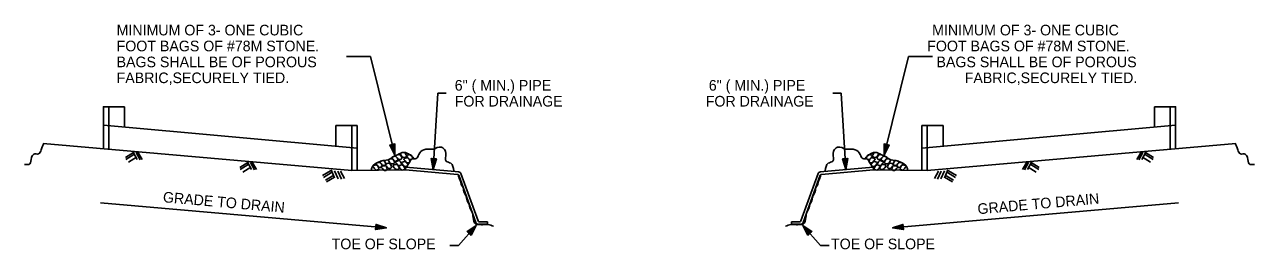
# Model space of a CAD drawing. Extents: x -41 to 191, y -168 to 6.
# Drawn here: x -40.56 to -7.34, y -129.27 to -123.2 of the extents above; entities that cross this region are included whole.
import ezdxf

# ---------------------------------------------------------------- set-up
doc = ezdxf.new("R2010")
doc.units = 0
for name, color, linetype in [('Arrowhead Terminators CELL', 7, 'Continuous'), ('Default', 7, 'Continuous'), ('Dimension Lines CELL', 7, 'Continuous'), ('Mis Object Lines', 7, 'Continuous'), ('Text CELL', 7, 'Continuous')]:
    doc.layers.add(name, color=color, linetype=linetype)

msp = doc.modelspace()

# ---------------------------------------------------------------- linework, layer by layer
at = {"layer": 'Arrowhead Terminators CELL'}
for points in [[(-30.624, -126.441), (-30.638, -126.445), (-30.554, -126.719), (-30.651, -126.448), (-30.665, -126.451), (-30.554, -126.719), (-30.679, -126.455), (-30.693, -126.458), (-30.554, -126.719), (-30.554, -126.424), (-30.568, -126.427), (-30.554, -126.719), (-30.582, -126.431), (-30.596, -126.434), (-30.554, -126.719), (-30.61, -126.438), (-30.693, -126.458), (-30.554, -126.424), (-30.554, -126.719), (-30.693, -126.458)], [(-17.277, -126.441), (-17.263, -126.445), (-17.347, -126.719), (-17.249, -126.448), (-17.236, -126.451), (-17.347, -126.719), (-17.222, -126.455), (-17.208, -126.458), (-17.347, -126.719), (-17.347, -126.424), (-17.333, -126.427), (-17.347, -126.719), (-17.319, -126.431), (-17.305, -126.434), (-17.347, -126.719), (-17.291, -126.438), (-17.208, -126.458), (-17.347, -126.424), (-17.347, -126.719), (-17.208, -126.458)], [(-29.507, -126.822), (-29.521, -126.821), (-29.524, -127.108), (-29.535, -126.82), (-29.549, -126.819), (-29.524, -127.108), (-29.564, -126.819), (-29.578, -126.818), (-29.524, -127.108), (-29.435, -126.826), (-29.449, -126.825), (-29.524, -127.108), (-29.464, -126.825), (-29.478, -126.824), (-29.524, -127.108), (-29.492, -126.823), (-29.578, -126.818), (-29.435, -126.826), (-29.524, -127.108), (-29.578, -126.818)], [(-18.394, -126.822), (-18.38, -126.821), (-18.377, -127.108), (-18.366, -126.82), (-18.352, -126.819), (-18.377, -127.108), (-18.337, -126.819), (-18.323, -126.818), (-18.377, -127.108), (-18.466, -126.826), (-18.452, -126.825), (-18.377, -127.108), (-18.437, -126.825), (-18.423, -126.824), (-18.377, -127.108), (-18.409, -126.823), (-18.323, -126.818), (-18.466, -126.826), (-18.377, -127.108), (-18.323, -126.818)], [(-31.073, -128.664), (-31.074, -128.679), (-30.787, -128.689), (-31.075, -128.693), (-31.076, -128.707), (-30.787, -128.689), (-31.077, -128.721), (-31.079, -128.736), (-30.787, -128.689), (-31.066, -128.593), (-31.068, -128.607), (-30.787, -128.689), (-31.069, -128.622), (-31.07, -128.636), (-30.787, -128.689), (-31.071, -128.65), (-31.079, -128.736), (-31.066, -128.593), (-30.787, -128.689), (-31.079, -128.736)], [(-28.553, -128.836), (-28.543, -128.845), (-28.364, -128.621), (-28.532, -128.855), (-28.521, -128.864), (-28.364, -128.621), (-28.511, -128.874), (-28.5, -128.883), (-28.364, -128.621), (-28.607, -128.788), (-28.596, -128.798), (-28.364, -128.621), (-28.586, -128.807), (-28.575, -128.817), (-28.364, -128.621), (-28.564, -128.826), (-28.5, -128.883), (-28.607, -128.788), (-28.364, -128.621), (-28.5, -128.883)], [(-19.348, -128.836), (-19.358, -128.845), (-19.537, -128.621), (-19.369, -128.855), (-19.38, -128.864), (-19.537, -128.621), (-19.39, -128.874), (-19.401, -128.883), (-19.537, -128.621), (-19.294, -128.788), (-19.305, -128.798), (-19.537, -128.621), (-19.315, -128.807), (-19.326, -128.817), (-19.537, -128.621), (-19.337, -128.826), (-19.401, -128.883), (-19.294, -128.788), (-19.537, -128.621), (-19.401, -128.883)], [(-16.828, -128.664), (-16.827, -128.679), (-17.114, -128.689), (-16.826, -128.693), (-16.825, -128.707), (-17.114, -128.689), (-16.824, -128.721), (-16.822, -128.736), (-17.114, -128.689), (-16.835, -128.593), (-16.833, -128.607), (-17.114, -128.689), (-16.832, -128.622), (-16.831, -128.636), (-17.114, -128.689), (-16.83, -128.65), (-16.822, -128.736), (-16.835, -128.593), (-17.114, -128.689), (-16.822, -128.736)]]:
    msp.add_lwpolyline(points, dxfattribs=at)
at = {"layer": 'Default'}
for p, q in [((-38.286, -126.575), (-38.286, -125.421)), ((-38.286, -125.421), (-37.857, -125.421)), ((-9.615, -125.421), (-10.044, -125.421)), ((-9.615, -126.575), (-9.615, -125.421)), ((-32.147, -125.927), (-31.717, -125.927)), ((-31.717, -125.927), (-31.717, -127.14)), ((-31.717, -125.927), (-31.574, -125.927)), ((-31.574, -125.927), (-31.574, -127.14)), ((-16.184, -125.927), (-16.327, -125.927)), ((-16.327, -125.927), (-16.327, -127.14)), ((-15.754, -125.927), (-16.184, -125.927)), ((-16.184, -125.927), (-16.184, -127.14)), ((-30.267, -127.122), (-31.723, -127.136)), ((-30.261, -127.051), (-30.267, -127.122)), ((-28.863, -127.245), (-30.267, -127.122)), ((-30.261, -127.051), (-28.834, -127.175)), ((-17.64, -127.051), (-19.067, -127.175)), ((-19.038, -127.245), (-17.634, -127.122)), ((-17.64, -127.051), (-17.634, -127.122)), ((-17.634, -127.122), (-16.178, -127.136)), ((-28.833, -127.268), (-28.368, -128.545)), ((-28.773, -127.222), (-28.309, -128.497)), ((-19.128, -127.222), (-19.592, -128.497)), ((-19.068, -127.268), (-19.533, -128.545)), ((-28.276, -128.521), (-28.055, -128.521)), ((-28.055, -128.521), (-28.055, -128.592)), ((-19.625, -128.521), (-19.846, -128.521)), ((-19.846, -128.521), (-19.846, -128.592)), ((-28.301, -128.592), (-28.055, -128.592)), ((-19.6, -128.592), (-19.846, -128.592))]:
    msp.add_line(p, q, dxfattribs=at)
for points in [[(-38.429, -126.558), (-38.429, -125.421), (-38.286, -125.421), (-38.286, -125.425)], [(-9.472, -126.558), (-9.472, -125.421), (-9.615, -125.421), (-9.615, -125.425)], [(-40.051, -126.408), (-31.723, -127.136)], [(-7.85, -126.408), (-16.178, -127.136)]]:
    msp.add_lwpolyline(points, dxfattribs=at)
for centre, radius, start, end in [((-28.841, -127.247), 0.0716, 20.0004, 85.0001), ((-19.06, -127.247), 0.0716, 94.9999, 159.9996), ((-28.866, -127.28), 0.0358, 20, 85), ((-19.035, -127.28), 0.0358, 95, 160), ((-28.276, -128.485), 0.0358, 200.0006, 270), ((-19.625, -128.485), 0.0358, 270, 339.9994), ((-28.301, -128.521), 0.0716, 200.0001, 270), ((-19.6, -128.521), 0.0716, 270, 339.9999)]:
    msp.add_arc(centre, radius, start, end, dxfattribs=at)
for points in [[(-40.037, -126.4), (-40.107, -126.58), (-40.177, -126.689), (-40.307, -126.699), (-40.367, -126.789), (-40.417, -126.959), (-40.557, -126.979)], [(-28.968, -127.144), (-29.047, -126.944), (-29.169, -126.889), (-29.181, -126.682), (-29.302, -126.506), (-29.527, -126.561), (-29.655, -126.561), (-29.776, -126.579), (-29.91, -126.707), (-29.983, -126.816), (-30.086, -126.828), (-30.165, -126.925), (-30.25, -127.047)], [(-18.933, -127.144), (-18.854, -126.944), (-18.732, -126.889), (-18.72, -126.682), (-18.599, -126.506), (-18.374, -126.561), (-18.246, -126.561), (-18.125, -126.579), (-17.991, -126.707), (-17.918, -126.816), (-17.815, -126.828), (-17.736, -126.925), (-17.651, -127.047)], [(-7.864, -126.4), (-7.794, -126.58), (-7.724, -126.689), (-7.594, -126.699), (-7.534, -126.789), (-7.484, -126.959), (-7.344, -126.979)], [(-30.05, -126.81), (-30.159, -126.707), (-30.305, -126.652), (-30.487, -126.713), (-30.597, -126.761), (-30.712, -126.84), (-30.87, -126.871), (-31.022, -126.925), (-31.156, -127.023), (-31.192, -127.12)], [(-30.566, -126.919), (-30.627, -126.828), (-30.682, -126.828), (-30.737, -126.865), (-30.718, -126.889), (-30.682, -126.932), (-30.639, -126.962), (-30.579, -126.944), (-30.566, -126.925)], [(-30.469, -126.853), (-30.53, -126.761), (-30.585, -126.761), (-30.639, -126.798), (-30.621, -126.822), (-30.585, -126.865), (-30.542, -126.895), (-30.481, -126.877), (-30.469, -126.859)], [(-30.378, -126.962), (-30.439, -126.871), (-30.493, -126.871), (-30.548, -126.907), (-30.53, -126.932), (-30.493, -126.974), (-30.451, -127.004), (-30.39, -126.986), (-30.378, -126.968)], [(-30.366, -126.804), (-30.427, -126.713), (-30.481, -126.713), (-30.536, -126.749), (-30.518, -126.774), (-30.481, -126.816), (-30.439, -126.846), (-30.378, -126.828), (-30.366, -126.81)], [(-30.244, -126.749), (-30.305, -126.658), (-30.36, -126.658), (-30.415, -126.694), (-30.396, -126.719), (-30.36, -126.761), (-30.317, -126.792), (-30.256, -126.774), (-30.244, -126.755)], [(-30.147, -126.889), (-30.208, -126.798), (-30.263, -126.798), (-30.317, -126.834), (-30.299, -126.859), (-30.263, -126.901), (-30.22, -126.932), (-30.159, -126.913), (-30.147, -126.895)], [(-30.074, -126.804), (-30.135, -126.713), (-30.19, -126.713), (-30.244, -126.749), (-30.226, -126.774), (-30.19, -126.816), (-30.147, -126.846), (-30.086, -126.828), (-30.074, -126.81)], [(-17.851, -126.81), (-17.742, -126.707), (-17.596, -126.652), (-17.414, -126.713), (-17.304, -126.761), (-17.189, -126.84), (-17.031, -126.871), (-16.879, -126.925), (-16.745, -127.023), (-16.709, -127.12)], [(-17.827, -126.804), (-17.766, -126.713), (-17.711, -126.713), (-17.657, -126.749), (-17.675, -126.774), (-17.711, -126.816), (-17.754, -126.846), (-17.815, -126.828), (-17.827, -126.81)], [(-17.754, -126.889), (-17.693, -126.798), (-17.638, -126.798), (-17.584, -126.834), (-17.602, -126.859), (-17.638, -126.901), (-17.681, -126.932), (-17.742, -126.913), (-17.754, -126.895)], [(-17.657, -126.749), (-17.596, -126.658), (-17.541, -126.658), (-17.486, -126.694), (-17.505, -126.719), (-17.541, -126.761), (-17.584, -126.792), (-17.644, -126.774), (-17.657, -126.755)], [(-17.535, -126.804), (-17.474, -126.713), (-17.42, -126.713), (-17.365, -126.749), (-17.383, -126.774), (-17.42, -126.816), (-17.462, -126.846), (-17.523, -126.828), (-17.535, -126.81)], [(-17.523, -126.962), (-17.462, -126.871), (-17.408, -126.871), (-17.353, -126.907), (-17.371, -126.932), (-17.408, -126.974), (-17.45, -127.004), (-17.511, -126.986), (-17.523, -126.968)], [(-17.432, -126.853), (-17.371, -126.761), (-17.316, -126.761), (-17.262, -126.798), (-17.28, -126.822), (-17.316, -126.865), (-17.359, -126.895), (-17.42, -126.877), (-17.432, -126.859)], [(-17.335, -126.919), (-17.274, -126.828), (-17.219, -126.828), (-17.164, -126.865), (-17.183, -126.889), (-17.219, -126.932), (-17.262, -126.962), (-17.322, -126.944), (-17.335, -126.925)], [(-30.986, -127.084), (-31.046, -126.992), (-31.101, -126.992), (-31.156, -127.029), (-31.138, -127.053), (-31.101, -127.096), (-31.059, -127.126), (-30.998, -127.108), (-30.986, -127.09)], [(-30.895, -127.017), (-30.955, -126.925), (-31.01, -126.925), (-31.065, -126.962), (-31.046, -126.986), (-31.01, -127.029), (-30.968, -127.059), (-30.907, -127.041), (-30.895, -127.023)], [(-30.797, -126.968), (-30.858, -126.877), (-30.913, -126.877), (-30.968, -126.913), (-30.949, -126.938), (-30.913, -126.98), (-30.87, -127.011), (-30.81, -126.992), (-30.797, -126.974)], [(-30.761, -127.096), (-30.822, -127.004), (-30.876, -127.004), (-30.931, -127.041), (-30.913, -127.065), (-30.876, -127.108), (-30.834, -127.138), (-30.773, -127.12), (-30.761, -127.102)], [(-30.645, -127.041), (-30.706, -126.95), (-30.761, -126.95), (-30.816, -126.986), (-30.797, -127.011), (-30.761, -127.053), (-30.718, -127.084), (-30.658, -127.065), (-30.645, -127.047)], [(-30.439, -127.071), (-30.5, -126.98), (-30.554, -126.98), (-30.609, -127.017), (-30.591, -127.041), (-30.554, -127.084), (-30.512, -127.114), (-30.451, -127.096), (-30.439, -127.077)], [(-30.287, -127.084), (-30.348, -126.992), (-30.402, -126.992), (-30.457, -127.029), (-30.439, -127.053), (-30.402, -127.096), (-30.36, -127.126), (-30.299, -127.108), (-30.287, -127.09)], [(-30.208, -126.992), (-30.269, -126.901), (-30.323, -126.901), (-30.378, -126.938), (-30.36, -126.962), (-30.323, -127.004), (-30.281, -127.035), (-30.22, -127.017), (-30.208, -126.998)], [(-17.693, -126.992), (-17.632, -126.901), (-17.578, -126.901), (-17.523, -126.938), (-17.541, -126.962), (-17.578, -127.004), (-17.62, -127.035), (-17.681, -127.017), (-17.693, -126.998)], [(-17.614, -127.084), (-17.553, -126.992), (-17.499, -126.992), (-17.444, -127.029), (-17.462, -127.053), (-17.499, -127.096), (-17.541, -127.126), (-17.602, -127.108), (-17.614, -127.09)], [(-17.462, -127.071), (-17.401, -126.98), (-17.347, -126.98), (-17.292, -127.017), (-17.31, -127.041), (-17.347, -127.084), (-17.389, -127.114), (-17.45, -127.096), (-17.462, -127.077)], [(-17.256, -127.041), (-17.195, -126.95), (-17.14, -126.95), (-17.085, -126.986), (-17.104, -127.011), (-17.14, -127.053), (-17.183, -127.084), (-17.243, -127.065), (-17.256, -127.047)], [(-17.14, -127.096), (-17.079, -127.004), (-17.025, -127.004), (-16.97, -127.041), (-16.988, -127.065), (-17.025, -127.108), (-17.067, -127.138), (-17.128, -127.12), (-17.14, -127.102)], [(-17.104, -126.968), (-17.043, -126.877), (-16.988, -126.877), (-16.933, -126.913), (-16.952, -126.938), (-16.988, -126.98), (-17.031, -127.011), (-17.091, -126.992), (-17.104, -126.974)], [(-17.006, -127.017), (-16.946, -126.925), (-16.891, -126.925), (-16.836, -126.962), (-16.854, -126.986), (-16.891, -127.029), (-16.933, -127.059), (-16.994, -127.041), (-17.006, -127.023)], [(-16.915, -127.084), (-16.854, -126.992), (-16.8, -126.992), (-16.745, -127.029), (-16.763, -127.053), (-16.8, -127.096), (-16.842, -127.126), (-16.903, -127.108), (-16.915, -127.09)], [(-28.846, -127.26), (-28.825, -127.333), (-28.798, -127.409), (-28.777, -127.451), (-28.761, -127.533), (-28.731, -127.573), (-28.691, -127.713), (-28.628, -127.852), (-28.585, -127.995), (-28.549, -128.056), (-28.543, -128.114), (-28.479, -128.253), (-28.442, -128.411), (-28.369, -128.591), (-28.257, -128.6), (-28.187, -128.603), (-28.108, -128.597), (-28.041, -128.6), (-27.962, -128.618), (-27.895, -128.642)], [(-19.055, -127.26), (-19.076, -127.333), (-19.103, -127.409), (-19.124, -127.451), (-19.14, -127.533), (-19.17, -127.573), (-19.21, -127.713), (-19.273, -127.852), (-19.316, -127.995), (-19.352, -128.056), (-19.358, -128.114), (-19.422, -128.253), (-19.459, -128.411), (-19.532, -128.591), (-19.644, -128.6), (-19.714, -128.603), (-19.793, -128.597), (-19.86, -128.6), (-19.939, -128.618), (-20.006, -128.642)]]:
    msp.add_spline(points, degree=3, dxfattribs=at)
at = {"layer": 'Dimension Lines CELL'}
for p, q in [((-31.861, -124.064), (-31.218, -124.064)), ((-31.218, -124.064), (-30.554, -126.719)), ((-16.683, -124.064), (-17.347, -126.719)), ((-16.04, -124.064), (-16.683, -124.064)), ((-29.4, -125.056), (-29.524, -127.108)), ((-29.171, -125.056), (-29.4, -125.056)), ((-18.73, -125.056), (-18.501, -125.056)), ((-18.501, -125.056), (-18.377, -127.108)), ((-37.616, -126.656), (-37.835, -126.789)), ((-37.604, -126.704), (-37.823, -126.838)), ((-37.531, -126.777), (-37.75, -126.911)), ((-37.628, -126.644), (-37.519, -126.838)), ((-37.543, -126.656), (-37.434, -126.85)), ((-37.494, -126.644), (-37.385, -126.838)), ((-10.407, -126.644), (-10.516, -126.838)), ((-10.358, -126.656), (-10.467, -126.85)), ((-10.273, -126.644), (-10.382, -126.838)), ((-10.37, -126.777), (-10.151, -126.911)), ((-10.297, -126.704), (-10.078, -126.838)), ((-10.285, -126.656), (-10.066, -126.789)), ((-34.529, -126.925), (-34.748, -127.059)), ((-34.517, -126.974), (-34.736, -127.108)), ((-34.444, -127.047), (-34.663, -127.181)), ((-34.541, -126.913), (-34.432, -127.108)), ((-34.456, -126.925), (-34.347, -127.12)), ((-34.407, -126.913), (-34.298, -127.108)), ((-32.293, -127.144), (-32.511, -127.278)), ((-32.268, -127.193), (-32.487, -127.327)), ((-32.28, -127.12), (-32.183, -127.339)), ((-32.183, -127.144), (-32.086, -127.363)), ((-32.098, -127.156), (-32.001, -127.375)), ((-32.025, -127.156), (-31.916, -127.351)), ((-15.876, -127.156), (-15.985, -127.351)), ((-15.803, -127.156), (-15.9, -127.375)), ((-15.718, -127.144), (-15.815, -127.363)), ((-15.621, -127.12), (-15.718, -127.339)), ((-15.633, -127.193), (-15.414, -127.327)), ((-15.608, -127.144), (-15.39, -127.278)), ((-13.493, -126.913), (-13.603, -127.108)), ((-13.445, -126.925), (-13.554, -127.12)), ((-13.36, -126.913), (-13.469, -127.108)), ((-13.457, -127.047), (-13.238, -127.181)), ((-13.384, -126.974), (-13.165, -127.108)), ((-13.372, -126.925), (-13.153, -127.059)), ((-32.207, -127.266), (-32.426, -127.4)), ((-32.183, -127.315), (-32.402, -127.448)), ((-15.718, -127.315), (-15.499, -127.448)), ((-15.694, -127.266), (-15.475, -127.4)), ((-38.507, -128.014), (-30.787, -128.689)), ((-9.394, -128.014), (-17.114, -128.689)), ((-28.841, -129.159), (-28.364, -128.621)), ((-19.06, -129.159), (-19.537, -128.621)), ((-29.07, -129.159), (-28.841, -129.159)), ((-18.831, -129.159), (-19.06, -129.159))]:
    msp.add_line(p, q, dxfattribs=at)
at = {"layer": 'Mis Object Lines'}
for p, q in [((-37.857, -125.421), (-37.857, -125.967)), ((-10.044, -125.421), (-10.044, -125.967)), ((-38.429, -125.915), (-31.574, -126.537)), ((-32.147, -125.927), (-32.147, -126.485)), ((-9.472, -125.915), (-16.327, -126.537)), ((-15.754, -125.927), (-15.754, -126.485))]:
    msp.add_line(p, q, dxfattribs=at)

# ---------------------------------------------------------------- texts
at = {"layer": 'Text CELL'}
for s, height, p in [('MINIMUM OF 3- ONE CUBIC', 0.28639, (-38.072, -123.493)), ('MINIMUM OF 3- ONE CUBIC', 0.28639, (-16.047, -123.493)), ('FOOT BAGS OF #78M STONE.', 0.28638, (-38.072, -123.922)), ('FOOT BAGS OF #78M STONE.', 0.28638, (-16.18, -123.922)), ('BAGS SHALL BE OF POROUS', 0.28638, (-38.072, -124.352)), ('BAGS SHALL BE OF POROUS', 0.28638, (-15.93, -124.352)), ('FABRIC,SECURELY TIED.', 0.28639, (-38.072, -124.781)), ('FABRIC,SECURELY TIED.', 0.28639, (-15.168, -124.781)), ('6" ( MIN.) PIPE', 0.28638, (-28.94, -124.983)), ('6" ( MIN.) PIPE', 0.28638, (-22.078, -124.983)), ('FOR DRAINAGE', 0.28638, (-28.94, -125.413)), ('FOR DRAINAGE', 0.28638, (-22.161, -125.413)), ('TOE OF SLOPE', 0.28638, (-32.264, -129.264)), ('TOE OF SLOPE', 0.28638, (-18.778, -129.264))]:
    msp.add_text(s, height=height, dxfattribs=at).set_placement(p)
for rotation, p in [(355.0003, (-36.829, -127.994)), (4.9997, (-14.81, -128.321))]:
    msp.add_text('GRADE TO DRAIN', height=0.28639, rotation=rotation, dxfattribs=at).set_placement(p)

doc.saveas('drawing.dxf')
